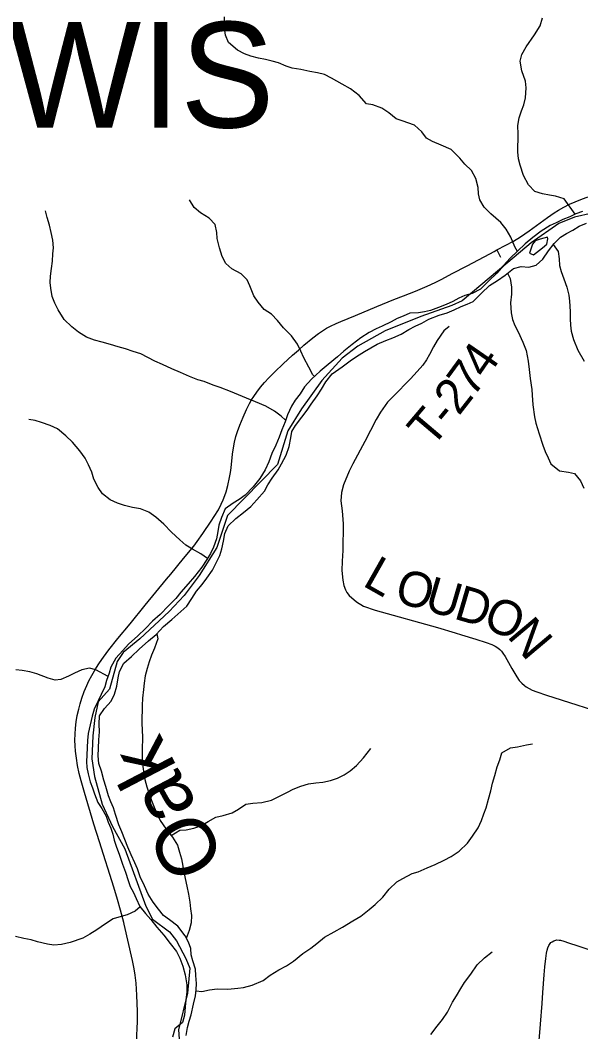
# Model space of a CAD drawing. Extents: x 1451455 to 1749751, y 218250 to 574981.
# Drawn here: x 1552286 to 1557069, y 300852 to 309481 of the extents above; entities that cross this region are included whole.
import ezdxf

# ---------------------------------------------------------------- set-up
doc = ezdxf.new("R2010")
doc.units = 0
for name, color, linetype in [('GM_X_Major_River', 7, 'Continuous'), ('GM_X_Major_River_Text', 7, 'Continuous'), ('GM_X_Minor_River', 7, 'Continuous'), ('GM_X_State_Route', 7, 'Continuous'), ('GM_X_Township', 7, 'Continuous'), ('GM_X_Township_Road', 7, 'Continuous'), ('GM_X_Township_Road_Text', 7, 'Continuous'), ('GM_X_Township_Text', 7, 'Continuous')]:
    doc.layers.add(name, color=color, linetype=linetype)

msp = doc.modelspace()

# ---------------------------------------------------------------- linework, layer by layer
at = {"layer": 'GM_X_Major_River'}
for points in [[(1557084, 307849.6), (1557027.8, 307828.4), (1556975.5, 307805.2), (1556917.3, 307780.1), (1556859, 307752.9), (1556808.7, 307729.7), (1556730.2, 307682.8), (1556661.5, 307627.8), (1556594.8, 307572.8), (1556530, 307511.7), (1556467.3, 307452.6), (1556408.4, 307389.5), (1556351.5, 307324.3), (1556284.7, 307257.2), (1556213.8, 307188.3), (1556143.3, 307149.3), (1556081.2, 307134.2), (1556029, 307109), (1555978.6, 307081.7), (1555920.4, 307056.6), (1555856.1, 307029.6), (1555787.9, 307004.6), (1555735.8, 306993.4), (1555683.8, 306986.1), (1555609.9, 306983.3), (1555553.6, 306956.1), (1555503.5, 306936.8), (1555451.1, 306907.6), (1555374.8, 306872.8), (1555324.5, 306849.5), (1555264.1, 306816.4), (1555193.6, 306773.4), (1555118.9, 306714.5), (1555048.2, 306659.5), (1554993.6, 306610.3), (1554912.7, 306543.5), (1554846, 306486.4), (1554771.1, 306419.5), (1554712.3, 306354.3), (1554673.5, 306294.9), (1554632.7, 306239.5), (1554600, 306187.9), (1554567, 306116.4), (1554546.1, 306056.6), (1554517.1, 305987), (1554496.2, 305923.3), (1554467.2, 305857.6), (1554434.2, 305784.1), (1554407.2, 305714.5), (1554376.2, 305646.9), (1554331.1, 305571.5), (1554274.2, 305500.3), (1554205.3, 305431.3), (1554154.8, 305394), (1554102.4, 305360.8), (1554035.8, 305313.8), (1554004.8, 305240.2), (1553981.8, 305174.5), (1553971, 305120.6), (1553960.1, 305058.7), (1553935.1, 304987), (1553910.3, 304933.4), (1553879.6, 304881.8), (1553834.6, 304814.5), (1553773.6, 304735.3), (1553718.7, 304674.1), (1553655.8, 304603), (1553613.1, 304549.6), (1553550.2, 304484.5), (1553479.3, 304411.5), (1553414.5, 304354.5), (1553355.7, 304291.3), (1553288.9, 304230.3), (1553209.9, 304157.5), (1553161.3, 304106.2), (1553102.4, 304039), (1553059.3, 303963.6), (1553044.5, 303911.8), (1553023.6, 303848.1), (1553008.8, 303796.3), (1552977.9, 303730.7), (1552951.1, 303675.1), (1552918.1, 303603.5), (1552901.2, 303543.8), (1552884.1, 303470), (1552867, 303398.2), (1552860.1, 303336.3), (1552857.2, 303276.3), (1552854.2, 303212.3), (1552851.4, 303158.3), (1552854.6, 303106.2), (1552865.7, 303052), (1552882.7, 302983.7), (1552901.8, 302933.4), (1552919, 302883.1), (1552947.8, 302808.7)], [(1553000.6, 303000), (1552979.8, 303074.3), (1552956.9, 303140.7), (1552951.9, 303206.8), (1552952.9, 303272.8), (1552958, 303342.8), (1552963, 303410.8), (1552960.1, 303476.8), (1552963.1, 303546.8), (1553004, 303610.2), (1553062.8, 303673.4), (1553089.7, 303731), (1553110.7, 303800.7), (1553121.7, 303870.6), (1553134.6, 303926.5), (1553169.6, 303996), (1553234.3, 304053), (1553301.1, 304116), (1553382, 304186.9), (1553444.7, 304242), (1553507.6, 304309), (1553578.4, 304368), (1553631, 304415.3), (1553707.9, 304484.1), (1553750.8, 304549.5), (1553791.6, 304611), (1553838.4, 304668.3), (1553877.1, 304721.7), (1553928.1, 304791), (1553954.9, 304846.6), (1553989.9, 304916.2), (1554006.7, 304972), (1554019.7, 305037.8), (1554030.6, 305101.7), (1554061.6, 305169.3), (1554126.4, 305230.3), (1554191, 305281.4), (1554253.7, 305334.5), (1554306.4, 305389.7), (1554369.4, 305464.8), (1554400.2, 305518.4), (1554436.9, 305573.9), (1554485.9, 305645.2), (1554516.6, 305696.8), (1554555.7, 305770.2), (1554580.8, 305845.9), (1554593.9, 305919.8), (1554604.7, 305973.7), (1554635.4, 306025.2), (1554690.4, 306096.5), (1554735.2, 306153.8), (1554769.9, 306207.3), (1554820.9, 306276.6), (1554855.7, 306334.2), (1554894.5, 306395.6), (1554947.5, 306464.9), (1555032.2, 306523.6), (1555100.8, 306574.6), (1555155.2, 306611.8), (1555223.8, 306654.8), (1555332.5, 306717.2), (1555404.8, 306748.2), (1555465, 306771.3), (1555537.4, 306804.2), (1555601.8, 306843.3), (1555656.1, 306870.5), (1555712.4, 306897.6), (1555772.8, 306930.7), (1555861.1, 306965.4), (1555929.3, 306986.4), (1555987.5, 307009.5), (1556049.8, 307038.6), (1556100, 307057.9), (1556152.3, 307083.1), (1556221.2, 307154.1), (1556290.1, 307219.1), (1556358.6, 307262.1), (1556423.1, 307307.2), (1556495.8, 307364.1), (1556560, 307381.2), (1556625.7, 307374.2), (1556689.8, 307391.2), (1556744.5, 307442.4), (1556793.5, 307513.7), (1556842.3, 307577), (1556897, 307630.2), (1556947.4, 307661.5), (1557001.7, 307690.7), (1557056.2, 307725.9), (1557118.4, 307751)], [(1556785.3, 307632), (1556723.1, 307612.9), (1556680.3, 307600), (1556656.7, 307571.9), (1556642, 307528), (1556632.7, 307493.2), (1556665.2, 307479.6)], [(1556665.2, 307479.6), (1556742, 307540.5), (1556778.4, 307572), (1556787.1, 307617.9), (1556785.3, 307632)], [(1553701.6, 300820.5), (1553714.6, 300888.3), (1553727.4, 300942.1), (1553744.2, 300997.9), (1553765.6, 301087.6), (1553780.7, 301159.4), (1553787.4, 301211.3), (1553790.3, 301265.3), (1553785.3, 301333.3), (1553782.1, 301385.4), (1553759.3, 301457.8), (1553744.1, 301508), (1553740.9, 301562.1), (1553721.8, 301616.4), (1553692.7, 301670.9), (1553630.1, 301753.9), (1553561.1, 301806.9), (1553509.8, 301845.7), (1553464.7, 301898.4), (1553419.7, 301959.1), (1553378.9, 302025.8), (1553346, 302098.3), (1553309.3, 302174.9), (1553286.4, 302243.3), (1553265.2, 302293.6), (1553232.3, 302362.2), (1553203.4, 302426.6), (1553153.5, 302559.4), (1553128.5, 302617.8), (1553099.9, 302706.3), (1553080.8, 302762.6), (1553059.7, 302815), (1553040.5, 302865.3), (1553017.8, 302945.7), (1553000.6, 303000)], [(1552947.8, 302808.7), (1552983, 302758.1), (1553019.9, 302691.5), (1553037.1, 302641.2), (1553058.2, 302588.9), (1553075.4, 302538.6), (1553088.6, 302486.4), (1553105.8, 302436.1), (1553132.5, 302357.7), (1553159.3, 302283.2), (1553184.2, 302214.8), (1553207, 302142.4), (1553224.2, 302092.2), (1553251.3, 302039.7), (1553274.5, 301989.3), (1553307.4, 301920.8), (1553354.4, 301862.1), (1553401.5, 301809.4), (1553450.4, 301744.6), (1553511.2, 301675.6), (1553566, 301604.8), (1553618.8, 301536), (1553647.9, 301481.5), (1553672.8, 301411.1), (1553693.6, 301338.8), (1553708.2, 301252.5), (1553707.4, 301194.5), (1553700.3, 301122.6), (1553693.4, 301064.7), (1553688.3, 300994.7), (1553669.4, 300931), (1553606.7, 300877.9), (1553585.6, 300806.2)]]:
    msp.add_lwpolyline(points, dxfattribs=at)
at = {"layer": 'GM_X_Minor_River'}
for points in [[(1556528.1, 307509.9), (1556507.7, 307547.8), (1556471.1, 307630.4), (1556432.3, 307699.1), (1556387.3, 307755.9), (1556302.5, 307829.3), (1556243.5, 307886.3), (1556206.6, 307949), (1556195.5, 308001.2), (1556192.3, 308053.3), (1556173.6, 308131.7), (1556136.8, 308198.4), (1556079.7, 308253.3), (1556036.6, 308304.1), (1555963.9, 308379.3), (1555878.6, 308416.7), (1555805.2, 308447.9), (1555751.6, 308474.8), (1555712.6, 308529.4), (1555651.6, 308586.5), (1555546.3, 308624.1), (1555494.6, 308639), (1555431.4, 308690), (1555372.2, 308731), (1555294.7, 308760.2), (1555240.9, 308769.1), (1555178.1, 308840.2), (1555103.1, 308895.4), (1555031.8, 308936.6), (1554940.8, 308988), (1554883.3, 309017), (1554823.6, 309031.9), (1554757.8, 309045), (1554680.1, 309060.2), (1554606.4, 309073.4), (1554554.7, 309088.2), (1554491.2, 309117.2), (1554435.5, 309132.1), (1554377.8, 309145), (1554318, 309158), (1554254.4, 309175), (1554198.8, 309195.9), (1554139.3, 309224.8), (1554064.4, 309290.1), (1554037.5, 309352.6), (1554026.9, 309436.9), (1554030.1, 309508.9)], [(1557022.1, 307825.9), (1556926.2, 307957.8), (1556854.6, 307980.9), (1556802.8, 307987.7), (1556743.1, 308000.7), (1556677.4, 308021.7), (1556622.4, 308078.6), (1556581.7, 308155.4), (1556553.2, 308244), (1556538.1, 308298.2), (1556531.1, 308358.4), (1556533.6, 308510.6), (1556532.9, 308584.7), (1556543.9, 308648.6), (1556562.9, 308708.4), (1556583.7, 308760.1), (1556596.7, 308818), (1556602.2, 308906), (1556597.1, 308962.2), (1556566.5, 309048.8), (1556551.9, 309133.1), (1556566.9, 309189), (1556601.9, 309254.5), (1556673.5, 309355.5), (1556722.8, 309432.9), (1556741.9, 309502.6)], [(1554796.5, 306442.1), (1554782.9, 306457.3), (1554748, 306521.9), (1554705.4, 306600.7), (1554680.3, 306657.1), (1554653.4, 306717.6), (1554600.6, 306790.5), (1554531.8, 306857.7), (1554480.8, 306918.5), (1554429.8, 306973.4), (1554366.5, 307014.4), (1554315.5, 307075.3), (1554278.5, 307129.9), (1554245.9, 307216.5), (1554222.8, 307267), (1554171.7, 307317.8), (1554090.5, 307361.1), (1554039.2, 307406), (1554010.3, 307466.5), (1553985.5, 307539), (1553966.8, 307619.4), (1553963.7, 307671.5), (1553950.8, 307739.8), (1553897.7, 307792.7), (1553824.6, 307837.9), (1553771.3, 307882.8), (1553730.5, 307949.5)], [(1554550.7, 306069.8), (1554511.3, 306103.1), (1554456, 306146), (1554382.8, 306189.2), (1554293.5, 306226.6), (1554218.1, 306257.8), (1554148.6, 306286.9), (1554079.1, 306314), (1553991.7, 306347.4), (1553932.1, 306368.4), (1553854.7, 306399.6), (1553802.9, 306412.4), (1553731.5, 306441.6), (1553654.1, 306476.8), (1553580.7, 306508), (1553501.4, 306545.3), (1553435.9, 306574.3), (1553374.5, 306605.3), (1553315, 306634.3), (1553249.4, 306655.3), (1553185.8, 306678.3), (1553122.2, 306695.3), (1553056.5, 306714.4), (1552984.9, 306735.5), (1552919.3, 306752.5), (1552851.7, 306777.6), (1552784.5, 306820.7), (1552727.3, 306865.6), (1552662.4, 306928.7), (1552609.8, 307009.6), (1552580.8, 307068.2), (1552559.7, 307124.6), (1552546.9, 307194.8), (1552541.7, 307245), (1552544.6, 307297), (1552551.7, 307363), (1552560.7, 307426.9), (1552565.7, 307488.9), (1552570.6, 307540.9), (1552563.7, 307605.1), (1552548.8, 307671.4), (1552535.8, 307733.7), (1552516.9, 307798.1), (1552501.9, 307856.4)], [(1556834.6, 307567), (1556876.8, 307508), (1556883.7, 307445.8), (1556886.8, 307387.7), (1556901.9, 307337.4), (1556924.9, 307274.9), (1556949.7, 307204.5), (1556966.6, 307136.1), (1556973.7, 307083.9), (1556978.2, 306995.8), (1556979.2, 306933.7), (1556982.3, 306881.5), (1556987.4, 306829.4), (1557008.2, 306757), (1557042.7, 306666.3), (1557099.1, 306573.4)], [(1556443.2, 307322.9), (1556467.3, 307278.1), (1556478, 307203.8), (1556479.1, 307145.7), (1556469.9, 307071.8), (1556476.4, 306985.6), (1556487.4, 306927.3), (1556506.6, 306877), (1556533.7, 306822.5), (1556574.2, 306735.7), (1556603, 306663.2), (1556621.5, 306572.8), (1556628.3, 306502.6), (1556637, 306426.4), (1556651.4, 306332.1), (1556654.6, 306282), (1556659.2, 306199.8), (1556673.6, 306099.5), (1556684.7, 306045.2), (1556713.1, 305952.7), (1556745.5, 305856.1), (1556764.6, 305801.7), (1556789.6, 305747.2), (1556814.8, 305696.8), (1556887.7, 305637.6), (1556963.5, 305626.4), (1557015.2, 305613.6), (1557066.2, 305552.7), (1557095.1, 305490.2)], [(1553884.5, 304890.1), (1553826.3, 304930.4), (1553755, 304969.5), (1553699.6, 305002.5), (1553648.4, 305049.3), (1553577.6, 305114.5), (1553512.7, 305181.5), (1553443.8, 305242.7), (1553384.6, 305285.6), (1553313.1, 305312.8), (1553243.3, 305325.9), (1553175.6, 305340.9), (1553116, 305361.9), (1553054.6, 305390.9), (1552989.5, 305441.9), (1552950.4, 305494.6), (1552915.6, 305565.2), (1552896.6, 305625.6), (1552869.6, 305688), (1552840.6, 305744.6), (1552795.7, 305809.3), (1552731, 305882.4), (1552675.9, 305937.3), (1552602.9, 305994.5), (1552541.5, 306025.5), (1552468, 306050.7), (1552414.3, 306065.5), (1552360.5, 306074.4)], [(1553450.6, 304248.2), (1553460.5, 304203.3), (1553433.2, 304125.7), (1553406.2, 304064), (1553385.3, 304008.3), (1553368.4, 303952.5), (1553353.4, 303888.7), (1553344.3, 303824.8), (1553337.4, 303772.8), (1553330.2, 303696.9), (1553327.1, 303634.9), (1553324.8, 303490.8), (1553327.6, 303420.7), (1553328.7, 303370.6), (1553326.8, 303252.5), (1553327.9, 303202.5), (1553330.8, 303136.4), (1553337.8, 303074.2), (1553350.6, 303004), (1553367.6, 302941.6), (1553386.5, 302881.3), (1553405.6, 302824.9), (1553428.6, 302768.5), (1553455.6, 302708.1), (1553480.7, 302653.6), (1553531.4, 302580.8), (1553586.2, 302511.9), (1553627.1, 302443.2), (1553646.1, 302384.9), (1553661.1, 302328.6), (1553681.3, 302218.2), (1553694.3, 302159.9), (1553707.2, 302093.7), (1553722, 302025.4), (1553732.9, 301957.2), (1553739.9, 301901), (1553746.9, 301842.9), (1553743.9, 301782.9), (1553728.8, 301715.1), (1553701.7, 301647.5)], [(1553035.3, 303883.6), (1552930.6, 303941.3), (1552876.8, 303954.1), (1552810.6, 303939.1), (1552750.2, 303910.1), (1552697.8, 303886.8), (1552633.4, 303857.8), (1552583.3, 303850.6), (1552525.6, 303867.5), (1552428.4, 303907), (1552368.7, 303922), (1552302.9, 303933), (1552249.1, 303939.8)], [(1553786, 301200.4), (1553836.1, 301197), (1553900.2, 301210), (1553966.3, 301219), (1554058.2, 301215.6), (1554142.3, 301224.3), (1554192.4, 301231.5), (1554264.6, 301250.4), (1554359.2, 301291), (1554418, 301336.1), (1554492.7, 301381), (1554559.1, 301413.9), (1554617.8, 301455.1), (1554696.8, 301519.9), (1554765.5, 301566.8), (1554818.2, 301606), (1554883, 301659.1), (1554965.7, 301705.8), (1555036.3, 301744.8), (1555125.1, 301799.4), (1555193.8, 301838.4), (1555262.6, 301895.4), (1555315.3, 301938.6), (1555380.3, 301999.6), (1555433.4, 302068.8), (1555500.4, 302131.8), (1555550.9, 302161.1), (1555629.5, 302201.9), (1555681.7, 302217.1), (1555758.2, 302251.9), (1555826.6, 302278.9), (1555903.2, 302317.7), (1555963.7, 302348.8), (1556032.3, 302391.8), (1556101.4, 302460.8), (1556146.4, 302520.1), (1556193.6, 302591.4), (1556222.6, 302655), (1556241.5, 302710.8), (1556262.4, 302762.5), (1556281.6, 302836.3), (1556302.8, 302908), (1556315.8, 302971.8), (1556334.9, 303039.6), (1556356.1, 303111.3), (1556377.1, 303173.1), (1556396.1, 303232.8), (1556468.8, 303275.7), (1556528.8, 303282.8), (1556605.1, 303299.6), (1556657.2, 303308.8)], [(1553575, 302526), (1553647.2, 302571), (1553703.2, 302576.1), (1553767.4, 302589.1), (1553827.7, 302610.2), (1553890.3, 302647.3), (1553954.8, 302684.3), (1554017, 302697.3), (1554093.3, 302720.2), (1554147.8, 302751.4), (1554212.5, 302794.4), (1554270.6, 302803.5), (1554348.6, 302808.3), (1554430.9, 302829), (1554505.4, 302865.9), (1554565.9, 302897), (1554616.3, 302922.2), (1554680.6, 302947.3), (1554744.9, 302968.3), (1554809, 302977.3), (1554867.1, 302982.4), (1554933.3, 302995.4), (1554993.6, 303016.5), (1555050, 303045.6), (1555102.5, 303078.8), (1555155.2, 303124), (1555214.3, 303189.2), (1555277.6, 303270.3)], [(1553310, 301917.6), (1553266, 301882.4), (1553199.5, 301851.4), (1553147.3, 301836.2), (1553079, 301817.2), (1553012.4, 301774.2), (1552939.5, 301721.3), (1552879, 301684.2), (1552820.5, 301651.1), (1552711.9, 301612.8), (1552637.7, 301595.9), (1552571.6, 301591), (1552519.8, 301599.8), (1552432.2, 301621.1), (1552378.5, 301636), (1552316.8, 301648.9), (1552247.1, 301666)], [(1555790.4, 300828.3), (1555843.6, 300901.6), (1555888.5, 300956.9), (1555931.5, 301020.3), (1555974.9, 301103.7), (1556007.8, 301159.2), (1556046.8, 301220.6), (1556077.6, 301272.2), (1556130.8, 301343.4), (1556186.1, 301422.6), (1556247, 301483.7), (1556311.8, 301534.7)]]:
    msp.add_lwpolyline(points, dxfattribs=at)
at = {"layer": 'GM_X_State_Route'}
for points in [[(1556293.6, 307489.8), (1556329, 307508.6), (1556354.3, 307521.9), (1556430.8, 307561.9), (1556494, 307597), (1556556.1, 307634), (1556629.8, 307683.7), (1556786.2, 307797.9), (1556842.3, 307837.5), (1556878.1, 307860.1), (1556923.5, 307886), (1556973, 307911.2), (1557020.6, 307932.8), (1557069, 307952.3), (1557115.2, 307968.5), (1557162.2, 307982.4), (1557215.9, 307996.2), (1557254.3, 308004.3)], [(1553535.1, 304713.7), (1553570.7, 304756.9), (1553679.4, 304888.3), (1553766.6, 304995.1), (1553796.1, 305034.7), (1553843.3, 305102), (1553914.8, 305208.1), (1553942, 305249.3), (1553976.8, 305305.2), (1554001.6, 305351.8), (1554019.2, 305391), (1554033.4, 305428), (1554043.8, 305459.3), (1554058.4, 305513.4), (1554073.1, 305581), (1554080, 305623.3), (1554085.1, 305662.5), (1554097.1, 305780), (1554104.8, 305835), (1554114.3, 305882.9), (1554126.8, 305930.2), (1554141, 305973.6), (1554160.4, 306025.7), (1554188.8, 306095.5), (1554218, 306161.3), (1554242.3, 306211.1), (1554260, 306242.3), (1554279.3, 306272.5), (1554305.7, 306309.8), (1554337.6, 306351.2), (1554371.3, 306391.2), (1554406.7, 306429.6), (1554459.8, 306483), (1554530.6, 306551.2), (1554610, 306624.6), (1554659.2, 306667.9), (1554706.3, 306708.6), (1554782.3, 306771), (1554831.4, 306808.9), (1554866.3, 306833), (1554899.6, 306853.4), (1554934.1, 306871.8), (1554981.2, 306894.3), (1555020.4, 306910.6), (1555147.9, 306962.8), (1555329.8, 307038.1), (1555475.4, 307098), (1555557.6, 307131), (1555658.4, 307170.4), (1555758.6, 307211.9), (1555827.2, 307243.6), (1555882.9, 307271.6), (1555972.7, 307319.5), (1556100.1, 307387.3), (1556293.6, 307489.8)], [(1553169.3, 301785.4), (1553142.8, 301889), (1553117.5, 301980.8), (1553086.1, 302084.6), (1552961.9, 302471.9), (1552914.9, 302622.1), (1552834.5, 302892.4), (1552806.2, 302993.4), (1552790.3, 303056.9), (1552775.7, 303124), (1552765, 303185.2), (1552757, 303246.7), (1552753.8, 303292.3), (1552752.7, 303341.2), (1552754.1, 303390.2), (1552758, 303442.3), (1552764.7, 303497.4), (1552773.2, 303549), (1552785.2, 303603.2), (1552797.2, 303650.6), (1552812.1, 303697.3), (1552833.1, 303755.7), (1552854.2, 303807.1), (1552872.1, 303845.6), (1552896.4, 303891.7), (1552931.2, 303951), (1552962.8, 304000.7), (1552996, 304049.3), (1553041, 304109.6), (1553118.9, 304206.8), (1553223.3, 304333.2), (1553351.6, 304491.2), (1553535.1, 304713.7)], [(1553278, 300757.7), (1553285.4, 300882.3), (1553286.8, 300938.1), (1553286.4, 301026.8), (1553280.7, 301164.6), (1553275.4, 301266.3), (1553267.6, 301335), (1553258.9, 301390.3), (1553244.8, 301461.3), (1553172.9, 301771.3), (1553169.3, 301785.4)]]:
    msp.add_lwpolyline(points, dxfattribs=at)
at = {"layer": 'GM_X_Township'}
msp.add_lwpolyline([(1557166.9, 307836.4), (1557015.4, 307801), (1556882.4, 307747.2), (1556646, 307583.1), (1556446.9, 307415.9), (1556055.7, 307087.6), (1555969.4, 307046.6), (1555703.3, 306953.2), (1555400.4, 306831.4), (1555166.8, 306701.2), (1555032.4, 306597.9), (1554861.1, 306408.2), (1554685.6, 306167.6), (1554569.5, 305977.9), (1554481.7, 305692), (1554054.3, 305256), (1553963.6, 304982.9), (1553813.6, 304743.7), (1553686.2, 304575.3), (1553557.4, 304438), (1553306.8, 304204.4), (1553165.3, 304087), (1553114.3, 304012), (1553047.8, 303775.6), (1552950.1, 303666.7), (1552923.3, 303533.9), (1552906.2, 303376.6), (1552896.3, 303179.9), (1552918.9, 303031.3), (1552984, 302795), (1553074.6, 302602.6), (1553179.3, 302413), (1553359, 301924.9), (1553414.2, 301813.1), (1553560, 301704.2), (1553619.4, 301629.2), (1553698.6, 301477.8), (1553732.6, 301395.7), (1553712.8, 301180.7), (1553636.3, 300869.5), (1553650.4, 300674.2)], dxfattribs=at)
msp.add_lwpolyline([(1557166.9, 307836.4), (1557015.4, 307801), (1556882.4, 307747.2), (1556646, 307583.1), (1556446.9, 307415.9), (1556055.7, 307087.6), (1555969.4, 307046.6), (1555703.3, 306953.2), (1555400.4, 306831.4), (1555166.8, 306701.2), (1555032.4, 306597.9), (1554861.1, 306408.2), (1554685.6, 306167.6), (1554569.5, 305977.9), (1554481.7, 305692), (1554054.3, 305256), (1553963.6, 304982.9), (1553813.6, 304743.7), (1553686.2, 304575.3), (1553557.4, 304438), (1553306.8, 304204.4), (1553165.3, 304087), (1553114.3, 304012), (1553047.8, 303775.6), (1552950.1, 303666.7), (1552923.3, 303533.9), (1552906.2, 303376.6), (1552896.3, 303179.9), (1552918.9, 303031.3), (1552984, 302795), (1553074.6, 302602.6), (1553179.3, 302413), (1553359, 301924.9), (1553414.2, 301813.1), (1553560, 301704.2), (1553619.4, 301629.2), (1553698.6, 301477.8), (1553732.6, 301395.7), (1553712.8, 301180.7), (1553636.3, 300869.5), (1553650.4, 300674.2)], dxfattribs=at)
at = {"layer": 'GM_X_Township_Road'}
for points in [[(1556354.3, 307521.9), (1556359.9, 307510.9), (1556373.3, 307484.3), (1556385, 307461.2)], [(1555945.9, 306869.9), (1555901.5, 306832.4), (1555843, 306750.6), (1555811.5, 306695.6), (1555778.7, 306628.9), (1555753.4, 306585.4), (1555720.2, 306540.1), (1555673.4, 306486.1), (1555616.1, 306422), (1555470, 306273.4), (1555421.1, 306223.1), (1555360, 306137.8), (1555324.1, 306074.6), (1555226.7, 305887.5), (1555123.8, 305698.1), (1555093.4, 305634.9), (1555045, 305517.7), (1555027.9, 305453.7), (1555023.2, 305382.3), (1555033.1, 305295.7), (1555041.3, 305185.1), (1555038.5, 304957.8), (1555034, 304867.2), (1555031.4, 304785.9), (1555037.6, 304704.6), (1555047.8, 304659.6), (1555060.7, 304622.2), (1555073.5, 304598.8), (1555093.4, 304574.3), (1555155.4, 304520.5), (1555213.9, 304484.2), (1555313.4, 304448.3), (1555845.6, 304301.2), (1555996, 304256.5), (1556050.4, 304239.6)], [(1556050.4, 304239.6), (1556174.3, 304201.1), (1556261.1, 304172.5), (1556310.3, 304154.8), (1556339.9, 304141.4), (1556362, 304127.8), (1556379.4, 304113.1), (1556392.7, 304098.8), (1556404.6, 304083.3), (1556424.1, 304053), (1556482.1, 303950.3), (1556523.4, 303879.6), (1556543.8, 303849.9), (1556565.2, 303825.2), (1556587.6, 303806.1), (1556603.6, 303794.8), (1556629.1, 303779.9), (1556655.7, 303767), (1556695.2, 303751.4), (1556775.4, 303724.2), (1557036.8, 303641.1), (1557177.5, 303597.2)], [(1556711, 300745), (1556726.5, 300916.7), (1556740.4, 301092.8), (1556745.9, 301187.7), (1556755.4, 301338.3), (1556761.2, 301406.8), (1556769.6, 301478.4), (1556776.5, 301524), (1556782.1, 301549.7), (1556787.6, 301568.6), (1556797, 301589.7), (1556802, 301598), (1556814.7, 301612.9), (1556824.9, 301620.9), (1556838.7, 301629.3), (1556847.9, 301632.2), (1556863.9, 301635.7), (1556883.5, 301635.2), (1556896.3, 301633.4), (1556925, 301625.9), (1556965.4, 301611.6), (1557043, 301585.2), (1557130.6, 301557.7)]]:
    msp.add_lwpolyline(points, dxfattribs=at)

# ---------------------------------------------------------------- texts
at = {"layer": 'GM_X_Major_River_Text'}
msp.add_text('Oak', height=499.83, rotation=117.5743, dxfattribs=at).set_placement((1554041.9, 302316.4))
at = {"layer": 'GM_X_Township_Road_Text'}
for s, rotation, p in [('4', 55.45007, (1556263.3, 306411.5)), ('7', 53.81464, (1556148.8, 306254.7)), ('2', 51.93381, (1556028.4, 306100.7)), ('T', 49.74803, (1555796.9, 305824.9)), ('-', 50.36948, (1555944.2, 305998.8)), ('L', 330.52436, (1555197.6, 304662.7)), ('O', 345.04971, (1555469.6, 304521)), ('U', 343.72836, (1555722.9, 304453.4)), ('D', 343.67357, (1555976.3, 304379.4)), ('O', 336.5644, (1556220.4, 304308.5)), ('N', 310.10385, (1556433.5, 304225.2))]:
    msp.add_text(s, height=300, rotation=rotation, dxfattribs=at).set_placement(p)
at = {"layer": 'GM_X_Township_Text'}
msp.add_text('LEWIS', height=900, rotation=0.00001, dxfattribs=at).set_placement((1550710, 308566.2))

doc.saveas('drawing.dxf')
